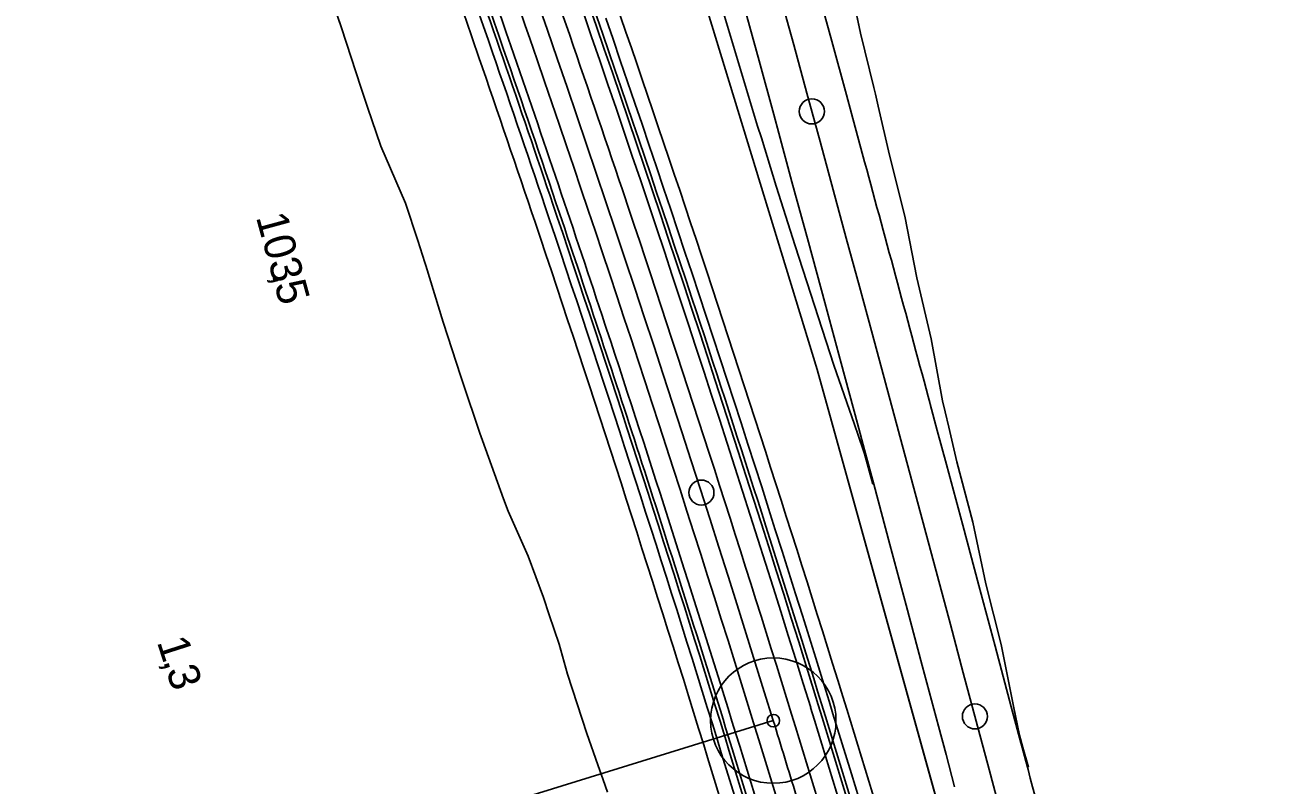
# Model space of a CAD drawing. Extents: x -678487 to -674601, y -1104811 to -1093295.
# Drawn here: x -676319.1 to -676120.1, y -1100215.5 to -1100094.2 of the extents above; entities that cross this region are included whole.
import ezdxf

# ---------------------------------------------------------------- set-up
doc = ezdxf.new("R2010")
doc.units = 0
for name, color, linetype in [('00_MiNGO', 7, 'Continuous'), ('SOxx02xx_Koleje_hlavní_body_Popis', 7, 'Continuous'), ('SOxx02xx_Koleje_hlavní_body_Popis10', 7, 'Continuous'), ('SOxx02xx_Staničení_Popis', 7, 'Continuous'), ('SOxx02xx_ŽSp_hrana', 7, 'Continuous'), ('SOxx02xx_ŽSp_násyp_plocha', 7, 'Continuous'), ('SOxx02xx_ŽSp_odvodnění', 7, 'Continuous'), ('SOxx02xx_ŽSp_zářez_hrana', 7, 'Continuous'), ('SOxx02xx_ŽSp_zářez_plocha', 7, 'Continuous'), ('SOxxxxxx_Osa_bod_P', 7, 'Continuous'), ('SOxxxxxx_Staničení_Popis', 7, 'Continuous'), ('SOxxxxxx_ŽSp_hrana', 7, 'Continuous'), ('SOxxxxxx_ŽSp_násyp_hrana', 7, 'Continuous'), ('SOxxxxxx_ŽSp_násyp_plocha', 7, 'Continuous')]:
    doc.layers.add(name, color=color, linetype=linetype)

msp = doc.modelspace()

# ---------------------------------------------------------------- linework, layer by layer
at = {"layer": '00_MiNGO'}
for p, q in [((-676192.76, -1100149.21), (-676227.95, -1100033.98)), ((-676171.39, -1100226.25), (-676192.76, -1100149.21))]:
    msp.add_line(p, q, dxfattribs=at)
at = {"layer": 'SOxx02xx_Koleje_hlavní_body_Popis'}
for q in [(-676257.09, -1100222.93), (-676199.76, -1100205.23)]:
    msp.add_line((-676199.76, -1100205.23), q, dxfattribs=at)
msp.add_circle((-676199.76, -1100205.23), 1, dxfattribs=at)
at = {"layer": 'SOxx02xx_Koleje_hlavní_body_Popis10'}
msp.add_line((-676199.76, -1100205.23), (-676199.76, -1100205.23), dxfattribs=at)
msp.add_circle((-676199.76, -1100205.23), 10, dxfattribs=at)
at = {"layer": 'SOxx02xx_Staničení_Popis'}
msp.add_circle((-676211.22, -1100168.83), 2, dxfattribs=at)
at = {"layer": 'SOxx02xx_ŽSp_hrana'}
msp.add_line((-676223.67, -1100120.99), (-676223.83, -1100120.52), dxfattribs=at)
for points in [[(-676048.99, -1100695.12), (-676098.21, -1100531.55), (-676121.24, -1100455), (-676132.31, -1100418.23), (-676144.27, -1100378.48), (-676155.78, -1100340.22), (-676170.18, -1100292.38), (-676181.16, -1100255.89), (-676184.59, -1100244.51), (-676187.47, -1100234.94), (-676189.32, -1100228.81), (-676190.37, -1100225.36), (-676193.28, -1100215.79), (-676196.21, -1100206.23), (-676196.84, -1100204.21)], [(-676202.69, -1100206.25), (-676202.07, -1100208.27), (-676199.14, -1100217.82), (-676196.23, -1100227.38), (-676195.19, -1100230.83), (-676193.34, -1100236.94), (-676190.46, -1100246.5), (-676187.04, -1100257.87), (-676176.07, -1100294.31), (-676161.69, -1100342.09), (-676150.19, -1100380.31), (-676138.25, -1100420), (-676127.2, -1100456.73), (-676104.19, -1100533.2), (-676017.42, -1100821.54)]]:
    msp.add_lwpolyline(points, dxfattribs=at)
for centre, radius, start, end in [((-679543.77, -1101237.56), 3502.82, 19.05102, 21.366), ((-679544.28, -1101237.79), 3497.18, 19.04918, 21.36502), ((-679543.77, -1101237.56), 3502.82, 18.59622, 19.05102), ((-679544.28, -1101237.79), 3497.18, 17.15526, 19.04918), ((-679543.77, -1101237.56), 3502.82, 17.15781, 18.58813)]:
    msp.add_arc(centre, radius, start, end, dxfattribs=at)
at = {"layer": 'SOxx02xx_ŽSp_násyp_plocha'}
msp.add_line((-676223.83, -1100120.52), (-676223.67, -1100120.99), dxfattribs=at)
at = {"layer": 'SOxx02xx_ŽSp_odvodnění'}
for p, q in [((-676234.39, -1100124.41), (-676234.23, -1100124.88)), ((-676206.94, -1100207.73), (-676206.32, -1100209.75)), ((-676206.32, -1100209.75), (-676203.39, -1100219.29))]:
    msp.add_line(p, q, dxfattribs=at)
for points in [[(-676193.35, -1100200.28), (-676192.59, -1100202.73), (-676191.97, -1100204.75), (-676189.03, -1100214.32), (-676186.11, -1100223.9), (-676185.07, -1100227.36), (-676183.21, -1100233.48), (-676180.32, -1100243.07), (-676178.04, -1100250.65), (-676171.67, -1100271.81), (-676163.02, -1100300.55), (-676154.38, -1100329.28), (-676144.29, -1100362.79), (-676136.14, -1100389.87), (-676127.79, -1100417.63)], [(-676192.07, -1100202.55), (-676191.45, -1100204.57), (-676188.51, -1100214.14), (-676185.59, -1100223.72), (-676184.55, -1100227.18), (-676182.69, -1100233.3), (-676179.8, -1100242.89), (-676177.52, -1100250.47), (-676171.15, -1100271.64), (-676162.5, -1100300.38), (-676153.85, -1100329.12), (-676143.77, -1100362.63), (-676135.62, -1100389.71), (-676127.26, -1100417.5)], [(-676207.46, -1100207.91), (-676206.84, -1100209.93), (-676203.91, -1100219.47), (-676201.01, -1100229.02), (-676199.97, -1100232.46), (-676198.12, -1100238.57), (-676195.24, -1100248.12), (-676191.82, -1100259.48), (-676183.7, -1100286.49), (-676175.13, -1100314.98), (-676166.51, -1100343.62), (-676157.89, -1100372.25), (-676149.28, -1100400.88), (-676140.66, -1100429.51), (-676132.05, -1100458.14), (-676123.43, -1100486.78), (-676114.81, -1100515.42), (-676109.06, -1100534.54), (-676103.3, -1100553.68), (-676022.3, -1100822.85)]]:
    msp.add_lwpolyline(points, dxfattribs=at)
for centre, radius, start, end in [((-679543.4, -1101237.4), 3506.92, 17.20156, 21.36671), ((-679543.35, -1101237.38), 3507.42, 18.2706, 21.3668), ((-679544.65, -1101237.95), 3493.09, 19.04784, 21.3643), ((-679544.7, -1101237.97), 3492.59, 18.59256, 19.40341), ((-679544.65, -1101237.95), 3493.09, 18.59274, 19.04784), ((-679544.69, -1101237.97), 3492.59, 17.15318, 18.58447), ((-679544.65, -1101237.95), 3493.09, 17.90346, 18.59274), ((-679543.35, -1101237.38), 3507.42, 17.15988, 18.2706), ((-679544.65, -1101237.95), 3493.09, 17.15341, 17.90346)]:
    msp.add_arc(centre, radius, start, end, dxfattribs=at)
at = {"layer": 'SOxx02xx_ŽSp_zářez_hrana'}
for p, q in [((-676271.68, -1100085.72), (-676268.64, -1100094.67)), ((-676268.64, -1100094.67), (-676265.55, -1100104.12)), ((-676265.55, -1100104.12), (-676264.86, -1100106.21)), ((-676264.86, -1100106.21), (-676264.49, -1100107.33)), ((-676264.49, -1100107.33), (-676262.38, -1100113.55)), ((-676262.38, -1100113.55), (-676258.42, -1100122.67)), ((-676258.42, -1100122.67), (-676256.48, -1100128.62)), ((-676235.43, -1100125.32), (-676235.59, -1100124.85)), ((-676256.48, -1100128.62), (-676255.34, -1100132.13)), ((-676255.34, -1100132.13), (-676255.19, -1100132.6)), ((-676255.19, -1100132.6), (-676252.39, -1100141.63)), ((-676252.39, -1100141.63), (-676249.6, -1100150.32)), ((-676226.61, -1100141.96), (-676226.36, -1100142.73)), ((-676249.6, -1100150.32), (-676249.35, -1100151.09)), ((-676249.35, -1100151.09), (-676246.56, -1100159.35)), ((-676246.56, -1100159.35), (-676246.14, -1100160.5)), ((-676246.14, -1100160.5), (-676242.77, -1100169.84)), ((-676242.77, -1100169.84), (-676242.06, -1100171.79)), ((-676242.06, -1100171.79), (-676238.88, -1100179)), ((-676238.88, -1100179), (-676236.42, -1100185.56)), ((-676236.42, -1100185.56), (-676235.49, -1100188.34)), ((-676235.49, -1100188.34), (-676233.93, -1100193.04)), ((-676233.93, -1100193.04), (-676232.57, -1100197.84)), ((-676232.57, -1100197.84), (-676229.5, -1100207.3)), ((-676229.5, -1100207.3), (-676227.74, -1100212.29)), ((-676227.74, -1100212.29), (-676226.89, -1100214.68)), ((-676226.89, -1100214.68), (-676226.19, -1100216.66))]:
    msp.add_line(p, q, dxfattribs=at)
for points in [[(-676190.86, -1100202.13), (-676190.24, -1100204.15), (-676187.3, -1100213.72), (-676184.38, -1100223.31), (-676183.33, -1100226.76), (-676181.48, -1100232.89), (-676178.59, -1100242.48), (-676176.31, -1100250.06), (-676169.93, -1100271.24), (-676164.17, -1100290.4), (-676158.4, -1100309.57), (-676149.75, -1100338.31), (-676141.1, -1100367.04), (-676132.46, -1100395.77), (-676126.01, -1100417.19)], [(-676188.67, -1100201.37), (-676188.05, -1100203.39), (-676185.11, -1100212.97), (-676182.19, -1100222.55), (-676181.14, -1100226.01), (-676179.29, -1100232.14), (-676176.39, -1100241.73), (-676174.11, -1100249.32), (-676167.73, -1100270.51), (-676161.96, -1100289.68), (-676156.19, -1100308.85), (-676147.54, -1100337.61), (-676138.89, -1100366.35), (-676132.18, -1100388.65), (-676127.35, -1100404.68), (-676123.76, -1100416.63)], [(-676193.8, -1100203.15), (-676193.17, -1100205.17), (-676190.24, -1100214.74), (-676187.32, -1100224.32), (-676186.28, -1100227.77), (-676184.43, -1100233.9), (-676181.54, -1100243.48), (-676179.25, -1100251.06), (-676169.96, -1100281.95), (-676161.36, -1100310.52), (-676152.71, -1100339.25), (-676144.07, -1100367.96), (-676135.43, -1100396.68), (-676129.03, -1100417.94)], [(-676023.53, -1100823.19), (-676104.53, -1100554.02), (-676110.29, -1100534.88), (-676116.04, -1100515.76), (-676127.53, -1100477.58), (-676136.15, -1100448.96), (-676144.31, -1100421.82), (-676150.5, -1100401.25), (-676159.12, -1100372.63), (-676167.73, -1100344), (-676176.34, -1100315.37), (-676184.91, -1100286.89), (-676193.04, -1100259.89), (-676196.45, -1100248.53), (-676199.33, -1100238.98), (-676201.18, -1100232.88), (-676202.22, -1100229.43), (-676205.12, -1100219.89), (-676208.05, -1100210.35), (-676208.67, -1100208.34)], [(-676205.73, -1100207.31), (-676205.11, -1100209.33), (-676202.18, -1100218.87), (-676199.28, -1100228.42), (-676198.23, -1100231.87), (-676196.39, -1100237.98), (-676193.51, -1100247.54), (-676190.09, -1100258.89), (-676181.96, -1100285.91), (-676173.38, -1100314.42), (-676164.76, -1100343.06), (-676156.14, -1100371.71), (-676147.53, -1100400.35), (-676138.91, -1100428.99), (-676130.29, -1100457.63), (-676121.67, -1100486.28), (-676110.17, -1100524.49), (-676104.41, -1100543.62), (-676020.53, -1100822.38)], [(-676025.78, -1100823.79), (-676106.77, -1100554.63), (-676112.53, -1100535.5), (-676118.28, -1100516.38), (-676126.89, -1100487.76), (-676132.63, -1100468.68), (-676138.37, -1100449.61), (-676144.11, -1100430.54), (-676149.85, -1100411.46), (-676154.65, -1100395.52), (-676161.33, -1100373.32), (-676169.94, -1100344.7), (-676178.55, -1100316.09), (-676184.29, -1100297), (-676190.03, -1100277.92), (-676195.24, -1100260.63), (-676198.65, -1100249.28), (-676201.53, -1100239.73), (-676203.37, -1100233.63), (-676204.41, -1100230.19), (-676207.32, -1100220.65), (-676210.24, -1100211.11), (-676210.86, -1100209.1)]]:
    msp.add_lwpolyline(points, dxfattribs=at)
for centre, radius, start, end in [((-679544.99, -1101238.11), 3489.31, 19.0466, 22.3606), ((-679543.06, -1101237.24), 3510.69, 18.59094, 21.36737), ((-679543.5, -1101237.44), 3505.75, 17.15913, 21.36651), ((-679544.8, -1101238.02), 3491.42, 19.04729, 21.36401), ((-679544.54, -1101237.91), 3494.25, 19.04822, 21.36451), ((-679543.25, -1101237.33), 3508.58, 17.16041, 19.03362), ((-679544.54, -1101237.91), 3494.25, 18.27893, 19.04822), ((-679544.99, -1101238.11), 3489.31, 18.59139, 19.0466), ((-679544.8, -1101238.02), 3491.42, 18.59215, 19.04729), ((-679543.06, -1101237.24), 3510.69, 17.16136, 18.59094), ((-679544.8, -1101238.02), 3491.42, 17.15265, 18.58405), ((-679544.99, -1101238.11), 3489.31, 17.15169, 18.59139), ((-679544.54, -1101237.91), 3494.25, 17.15393, 18.26561)]:
    msp.add_arc(centre, radius, start, end, dxfattribs=at)
at = {"layer": 'SOxx02xx_ŽSp_zářez_plocha'}
msp.add_line((-676227.95, -1100033.98), (-676192.76, -1100149.21), dxfattribs=at)
for points in [[(-676226.19, -1100216.66), (-676226.89, -1100214.68), (-676227.74, -1100212.29), (-676229.5, -1100207.3), (-676232.57, -1100197.84), (-676233.93, -1100193.04), (-676235.49, -1100188.34), (-676236.42, -1100185.56), (-676238.88, -1100179), (-676242.06, -1100171.79), (-676242.77, -1100169.84), (-676246.14, -1100160.5), (-676246.56, -1100159.35), (-676249.35, -1100151.09), (-676249.6, -1100150.32), (-676252.39, -1100141.63), (-676255.19, -1100132.6), (-676255.34, -1100132.13), (-676256.48, -1100128.62), (-676258.42, -1100122.67), (-676262.38, -1100113.55), (-676264.49, -1100107.33), (-676264.86, -1100106.21), (-676265.55, -1100104.12), (-676268.64, -1100094.67), (-676271.68, -1100085.72)], [(-676192.76, -1100149.21), (-676171.39, -1100226.25), (-676122.12, -1100416.22)], [(-676123.76, -1100416.63), (-676127.35, -1100404.68), (-676132.18, -1100388.65), (-676138.89, -1100366.35), (-676147.54, -1100337.61), (-676156.19, -1100308.85), (-676161.96, -1100289.68), (-676167.73, -1100270.51), (-676174.11, -1100249.32), (-676176.39, -1100241.73), (-676179.29, -1100232.14), (-676181.14, -1100226.01), (-676182.19, -1100222.55), (-676185.11, -1100212.97), (-676188.05, -1100203.39), (-676188.67, -1100201.37)], [(-676210.86, -1100209.1), (-676210.24, -1100211.11), (-676207.32, -1100220.65), (-676204.41, -1100230.19), (-676203.37, -1100233.63), (-676201.53, -1100239.73), (-676198.65, -1100249.28), (-676195.24, -1100260.63), (-676190.03, -1100277.92), (-676184.29, -1100297), (-676178.55, -1100316.09), (-676169.94, -1100344.7), (-676161.33, -1100373.32), (-676154.65, -1100395.52), (-676149.85, -1100411.46), (-676144.11, -1100430.54), (-676138.37, -1100449.61), (-676132.63, -1100468.68), (-676126.89, -1100487.76), (-676118.28, -1100516.38), (-676112.53, -1100535.5), (-676106.77, -1100554.63), (-676042.65, -1100767.7)]]:
    msp.add_lwpolyline(points, dxfattribs=at)
for centre, radius, start, end in [((-679544.99, -1101238.11), 3489.31, 19.0466, 22.3606), ((-679543.06, -1101237.24), 3510.69, 18.59094, 21.36737), ((-679544.99, -1101238.11), 3489.31, 18.59139, 19.0466), ((-679543.06, -1101237.24), 3510.69, 17.16136, 18.59094), ((-679544.99, -1101238.11), 3489.31, 17.15169, 18.59139)]:
    msp.add_arc(centre, radius, start, end, dxfattribs=at)
at = {"layer": 'SOxxxxxx_Osa_bod_P'}
for centre, radius, start, end in [((-693563.22, -1104838.51), 18002.25, 14.227837, 20.731742), ((-679544.02, -1101237.67), 3500, 17.15654, 27.27761)]:
    msp.add_arc(centre, radius, start, end, dxfattribs=at)
msp.add_open_spline([(-676199.76, -1100205.23), (-676198.54, -1100209.21), (-676196.09, -1100217.18), (-676192.46, -1100229.14), (-676188.84, -1100241.11), (-676186.44, -1100249.09), (-676185.24, -1100253.08)], degree=3, dxfattribs=at)
at = {"layer": 'SOxxxxxx_Staničení_Popis'}
for p, q in [((-676193.61, -1100108), (-676193.61, -1100108)), ((-676211.22, -1100168.83), (-676211.22, -1100168.83)), ((-676167.6, -1100204.56), (-676167.6, -1100204.56))]:
    msp.add_line(p, q, dxfattribs=at)
for centre in [(-676193.61, -1100108), (-676211.22, -1100168.83), (-676167.6, -1100204.56)]:
    msp.add_circle(centre, 2, dxfattribs=at)
at = {"layer": 'SOxxxxxx_ŽSp_hrana'}
for points in [[(-676217.05, -1100000.34), (-676216.22, -1100003.31), (-676215.13, -1100007.25), (-676214.37, -1100009.98), (-676211.69, -1100019.61), (-676209.01, -1100029.25), (-676206.34, -1100038.89), (-676203.68, -1100048.54), (-676202.09, -1100054.31), (-676201.02, -1100058.18), (-676198.37, -1100067.82), (-676195.72, -1100077.47), (-676193.08, -1100087.12), (-676190.44, -1100096.77), (-676188.1, -1100105.36), (-676187.3, -1100108.32), (-676185.19, -1100116.07)], [(-676204.68, -1100090.29), (-676202.04, -1100099.93), (-676199.7, -1100108.52), (-676198.9, -1100111.47), (-676196.79, -1100119.22), (-676194.17, -1100128.87), (-676191.55, -1100138.52), (-676188.95, -1100148.17), (-676186.34, -1100157.82), (-676185.21, -1100162.03), (-676183.75, -1100167.48), (-676181.15, -1100177.13), (-676178.57, -1100186.79), (-676175.99, -1100196.45), (-676173.41, -1100206.1), (-676172.2, -1100210.66), (-676170.84, -1100215.77)], [(-676174.74, -1100154.7), (-676173.6, -1100158.91), (-676172.14, -1100164.36), (-676169.54, -1100174.02), (-676166.96, -1100183.68), (-676164.37, -1100193.35), (-676161.8, -1100203.01), (-676160.58, -1100207.57)]]:
    msp.add_lwpolyline(points, dxfattribs=at)
for start, end in [(15.07555, 15.202859), (14.75728, 14.901402)]:
    msp.add_arc((-693563.22, -1104838.51), 18008.26, start, end, dxfattribs=at)
at = {"layer": 'SOxxxxxx_ŽSp_násyp_hrana'}
for p, q in [((-676187.95, -1100085.72), (-676185.84, -1100095.51)), ((-676208.02, -1100091.21), (-676205.17, -1100100.79)), ((-676185.84, -1100095.51), (-676183.74, -1100104.17)), ((-676205.17, -1100100.79), (-676202.59, -1100109.31)), ((-676183.74, -1100104.17), (-676183.48, -1100105.24)), ((-676183.48, -1100105.24), (-676183.04, -1100107.16)), ((-676183.04, -1100107.16), (-676181.25, -1100115)), ((-676202.59, -1100109.31), (-676202.26, -1100110.36)), ((-676202.26, -1100110.36), (-676201.66, -1100112.23)), ((-676201.66, -1100112.23), (-676199.32, -1100119.91)), ((-676181.25, -1100115), (-676178.77, -1100124.7)), ((-676199.32, -1100119.91), (-676196.29, -1100129.45)), ((-676178.77, -1100124.7), (-676176.88, -1100134.55)), ((-676196.29, -1100129.45), (-676193.2, -1100138.97)), ((-676176.88, -1100134.55), (-676174.58, -1100144.29)), ((-676193.2, -1100138.97), (-676190.09, -1100148.48)), ((-676174.58, -1100144.29), (-676172.77, -1100154.17)), ((-676190.09, -1100148.48), (-676186.8, -1100157.95)), ((-676172.77, -1100154.17), (-676172.34, -1100155.93)), ((-676172.34, -1100155.93), (-676171.74, -1100158.41)), ((-676186.8, -1100157.95), (-676186.21, -1100159.66)), ((-676171.74, -1100158.41), (-676170.5, -1100163.92)), ((-676186.21, -1100159.66), (-676185.39, -1100162.08)), ((-676185.39, -1100162.08), (-676183.88, -1100167.51)), ((-676170.5, -1100163.92), (-676167.91, -1100173.58)), ((-676167.91, -1100173.58), (-676165.86, -1100183.39)), ((-676165.86, -1100183.39), (-676163.4, -1100193.08)), ((-676163.4, -1100193.08), (-676161.43, -1100202.91)), ((-676161.43, -1100202.91), (-676160.51, -1100207.55)), ((-676160.51, -1100207.55), (-676159.98, -1100209.53)), ((-676159.98, -1100209.53), (-676159.08, -1100212.64))]:
    msp.add_line(p, q, dxfattribs=at)
at = {"layer": 'SOxxxxxx_ŽSp_násyp_plocha'}
for points in [[(-676217.05, -1100000.34), (-676216.22, -1100003.31), (-676215.13, -1100007.25), (-676214.37, -1100009.98), (-676211.69, -1100019.61), (-676209.01, -1100029.25), (-676206.34, -1100038.89), (-676203.68, -1100048.54), (-676202.09, -1100054.31), (-676201.02, -1100058.18), (-676198.37, -1100067.82), (-676195.72, -1100077.47), (-676193.08, -1100087.12), (-676190.44, -1100096.77), (-676188.1, -1100105.36), (-676187.3, -1100108.32), (-676185.19, -1100116.07)], [(-676184.46, -1100164.83), (-676185.21, -1100162.03), (-676186.34, -1100157.82), (-676188.95, -1100148.17), (-676191.55, -1100138.52), (-676194.17, -1100128.87), (-676196.79, -1100119.22), (-676198.9, -1100111.47), (-676199.7, -1100108.52), (-676202.04, -1100099.93), (-676204.68, -1100090.29), (-676207.32, -1100080.65), (-676209.96, -1100071.01), (-676212.61, -1100061.37), (-676213.68, -1100057.51), (-676215.27, -1100051.73), (-676217.93, -1100042.1), (-676220.6, -1100032.46), (-676223.27, -1100022.83), (-676225.95, -1100013.2), (-676226.71, -1100010.47), (-676227.8, -1100006.54), (-676228.63, -1100003.57)], [(-676160.26, -1100208.77), (-676161.43, -1100202.91), (-676163.4, -1100193.08), (-676165.86, -1100183.39), (-676167.91, -1100173.58), (-676170.5, -1100163.92), (-676171.74, -1100158.41), (-676172.34, -1100155.93), (-676172.77, -1100154.17), (-676174.58, -1100144.29), (-676176.88, -1100134.55), (-676178.77, -1100124.7), (-676181.25, -1100115), (-676183.04, -1100107.16), (-676183.48, -1100105.24), (-676183.74, -1100104.17), (-676185.84, -1100095.51), (-676187.95, -1100085.72)], [(-676208.02, -1100091.21), (-676205.17, -1100100.79), (-676202.59, -1100109.31), (-676202.26, -1100110.36), (-676201.66, -1100112.23), (-676199.32, -1100119.91), (-676196.29, -1100129.45), (-676193.2, -1100138.97), (-676190.09, -1100148.48), (-676186.8, -1100157.95), (-676186.21, -1100159.66), (-676184.46, -1100164.83)], [(-676174.74, -1100154.7), (-676173.6, -1100158.91), (-676172.14, -1100164.36), (-676169.54, -1100174.02), (-676166.96, -1100183.68), (-676164.37, -1100193.35), (-676161.8, -1100203.01), (-676160.26, -1100208.77)]]:
    msp.add_lwpolyline(points, dxfattribs=at)
msp.add_arc((-693563.22, -1104838.51), 18008.26, 15.07555, 15.202859, dxfattribs=at)

# ---------------------------------------------------------------- texts
at = {"layer": 'SOxx02xx_Staničení_Popis'}
for s, p in [('1', (-676298.1, -1100192.65)), (',', (-676297.12, -1100195.69)), ('3', (-676296.64, -1100197.2))]:
    msp.add_text(s, height=5, rotation=287.7813, dxfattribs=at).set_placement(p)
at = {"layer": 'SOxxxxxx_Staničení_Popis'}
for s, rotation, p in [('103', 285.2347, (-676282.3, -1100124.85)), (',', 285.2347, (-676279.79, -1100134.07)), ('5', 285.2347, (-676279.37, -1100135.61)), ('1', 287.7813, (-676298.1, -1100192.65)), (',', 287.7813, (-676297.12, -1100195.69)), ('3', 287.7813, (-676296.64, -1100197.2))]:
    msp.add_text(s, height=5, rotation=rotation, dxfattribs=at).set_placement(p)

doc.saveas('drawing.dxf')
